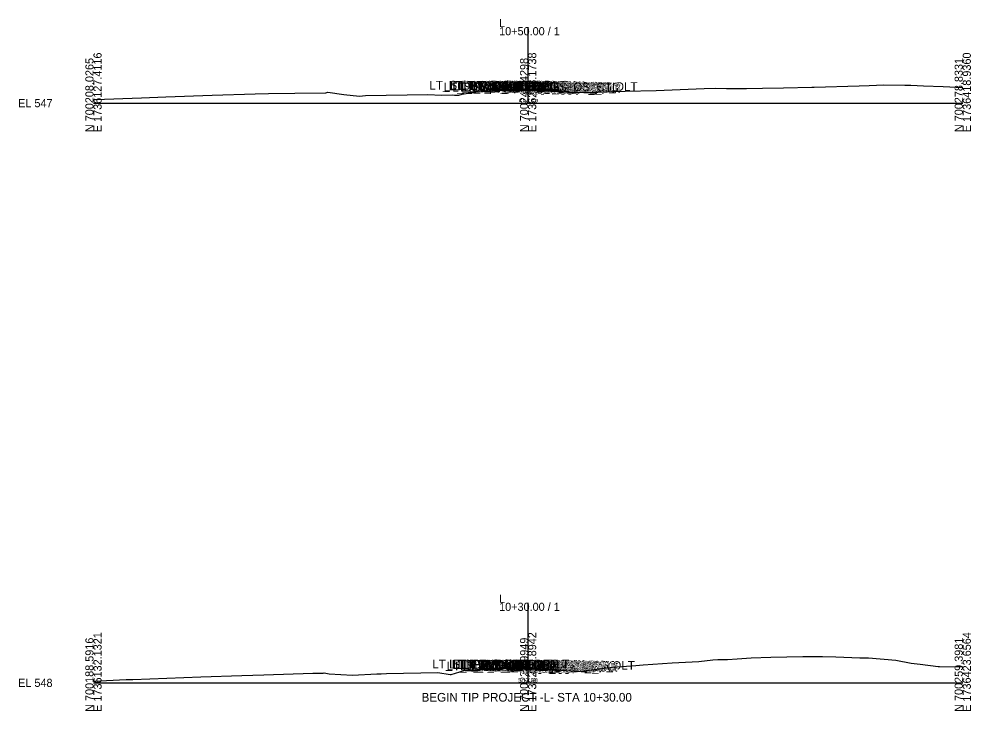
# Model space of a CAD drawing. Extents: x -26 to 697, y -10 to 2642.
# Drawn here: x -25.7 to 302.8, y -9.7 to 229 of the extents above; entities that cross this region are included whole.
import ezdxf

# ---------------------------------------------------------------- set-up
doc = ezdxf.new("R2010")
doc.units = 0
for name, color, linetype in [('Default', 7, 'Continuous'), ('Exist CMT Pavement', 7, 'Continuous'), ('Exist Cross Section Cell', 7, 'Continuous'), ('Exist XS Center Line Elevation Label', 7, 'Continuous'), ('Exist XS Ground Line', 7, 'Continuous'), ('Prop CMT Pvmt Course 1', 7, 'Continuous'), ('Prop CMT Pvmt Course 1 Wedge', 7, 'Continuous'), ('Prop CMT Pvmt Course 2', 7, 'Continuous'), ('Prop CMT Pvmt Course 2 Wedge', 7, 'Continuous'), ('Prop CMT Pvmt Surface', 7, 'Continuous'), ('Prop CMT Pvmt Surface Shoulder', 7, 'Continuous'), ('Prop CMT Pvmt Wedge Surface 1', 7, 'Continuous'), ('Prop CMT Pvmt Wedge Surface 2', 7, 'Continuous'), ('Prop CMT Shld Paved Course 1', 7, 'Continuous'), ('Prop CMT Shld Paved Course 2', 7, 'Continuous'), ('Prop CMT Slope Grass', 7, 'Continuous'), ('Prop CMT Subgrade Earthwork', 7, 'Continuous'), ('Prop XS SE Text', 7, 'Continuous'), ('Prop XS Side Slope Text', 7, 'Continuous'), ('Scratch_Level_1', 7, 'Continuous')]:
    doc.layers.add(name, color=color, linetype=linetype)

msp = doc.modelspace()

# ---------------------------------------------------------------- linework, layer by layer
at = {"layer": 'Exist CMT Pavement'}
for points in [[(150, 204.52), (140.21, 204.48)], [(140.21, 204.48), (145.1, 204.51)], [(145.1, 204.51), (150, 204.52)], [(155.38, 204.29), (150, 204.52)], [(150, 204.52), (160.77, 204.03)], [(160.77, 204.03), (155.38, 204.29)], [(150, 4.9), (140.24, 4.96)], [(140.24, 4.96), (145.12, 4.92)], [(145.12, 4.92), (150, 4.9)], [(154.91, 4.71), (150, 4.9)], [(150, 4.9), (159.83, 4.53)], [(159.83, 4.53), (154.91, 4.71)]]:
    msp.add_lwpolyline(points, dxfattribs=at)
at = {"layer": 'Exist Cross Section Cell'}
for p, q in [((150, 200), (150, 226.23)), ((0, 200), (150, 200)), ((150, 200), (300, 200)), ((150, 0), (150, 27.64)), ((0, 0), (150, 0)), ((150, 0), (300, 0))]:
    msp.add_line(p, q, dxfattribs=at)
at = {"layer": 'Exist XS Ground Line'}
for points in [[(0, 201.19), (0.59, 201.22), (16.62, 201.84), (24.98, 202.15), (40.94, 202.76), (55.81, 203.19), (60.46, 203.29), (69.46, 203.51), (80.19, 203.56), (80.83, 203.83), (86.45, 202.94), (91.86, 202.43), (93.87, 202.68), (115.45, 202.98), (120.08, 202.81), (123.78, 202.88), (124.56, 202.76), (126.09, 202.82), (127.21, 203.16), (130.72, 203.71), (134.46, 203.98), (140.21, 204.48), (141.2, 204.51), (149.87, 204.52), (151.5, 204.47), (162.09, 203.97), (165.52, 203.65), (172.32, 203.77), (174.03, 203.8), (180.31, 204), (183.46, 204.11), (194.19, 204.38), (210.71, 205.05), (214.65, 205.13), (218.43, 205.05), (225.41, 205.12), (230.86, 205.17), (238.16, 205.27), (247.87, 205.55), (248.69, 205.57), (264.2, 205.98), (267.71, 206.15), (272.78, 206.28), (280.07, 206.2), (282.14, 206.2), (286.51, 206.02), (293.22, 205.7), (300, 205.41)], [(0, 0.56), (11.33, 1.13), (13.59, 1.21), (37.02, 2.08), (51.16, 2.57), (58.82, 2.79), (75.74, 3.33), (79.3, 3.3), (79.63, 3.44), (81.37, 3.16), (89.44, 2.63), (97.84, 3.1), (99.33, 3.15), (101.12, 3.22), (118.87, 3.55), (123.13, 2.86), (123.44, 2.87), (127.98, 4.24), (128.94, 4.54), (135.7, 4.68), (140.24, 4.96), (141.9, 4.93), (149.9, 4.9), (158.4, 4.57), (159.83, 4.53), (160.25, 4.51), (162.4, 4.27), (164.5, 4.12), (167.14, 3.91), (172.89, 4.64), (176.41, 5.08), (179.14, 5.37), (187.14, 6.02), (189.66, 6.25), (199.74, 6.92), (208.96, 7.42), (213.75, 7.94), (215.52, 8.07), (218.79, 8.06), (222.17, 8.31), (226.93, 8.66), (233.76, 8.88), (244.87, 9.1), (250.06, 9.07), (251.57, 9.07), (256.23, 8.98), (264.51, 8.66), (267.45, 8.62), (276.88, 7.8), (282.24, 6.75), (285.31, 6.42), (291.52, 5.68), (291.94, 5.61), (300, 5.51)]]:
    msp.add_lwpolyline(points, dxfattribs=at)
at = {"layer": 'Prop CMT Pvmt Course 1'}
for points in [[(150, 204.77), (139.25, 204.78)], [(139.25, 204.78), (139.25, 204.57)], [(139.25, 204.57), (140.21, 204.57)], [(140.21, 204.57), (140.21, 204.67)], [(140.21, 204.67), (150, 204.67)], [(150, 204.56), (150, 204.77)], [(150, 204.77), (160.77, 204.35)], [(150, 204.56), (150, 204.77)], [(150, 204.67), (150, 204.56), (150, 204.56)], [(160.77, 204.25), (150, 204.67)], [(150, 204.67), (150, 204.56), (150, 204.56)], [(160.77, 204.35), (160.77, 204.14), (160.77, 204.14), (160.77, 204.25)], [(150, 5), (140.24, 5.04)], [(140.24, 5.04), (140.24, 4.83), (140.24, 4.83), (140.24, 4.93)], [(140.24, 4.93), (150, 4.9)], [(150, 4.8), (150, 5)], [(150, 5), (159.83, 4.62)], [(150, 4.8), (150, 5)], [(150, 4.9), (150, 4.8), (150, 4.8)], [(159.83, 4.52), (150, 4.9)], [(150, 4.9), (150, 4.8), (150, 4.8)], [(159.83, 4.62), (159.83, 4.41), (159.83, 4.41), (159.83, 4.52)]]:
    msp.add_lwpolyline(points, dxfattribs=at)
at = {"layer": 'Prop CMT Pvmt Course 1 Wedge'}
for points in [[(150, 204.67), (140.21, 204.67)], [(150, 204.67), (160.77, 204.25)], [(150, 4.9), (140.24, 4.93)], [(150, 4.9), (159.83, 4.52)]]:
    msp.add_lwpolyline(points, dxfattribs=at)
at = {"layer": 'Prop CMT Pvmt Course 2'}
for points in [[(140.21, 204.57), (139.25, 204.57)], [(139.25, 204.57), (139.25, 204.11)], [(139.25, 204.11), (140.21, 204.11)], [(140.21, 204.11), (140.21, 204.57)], [(160.77, 203.69), (160.77, 203.69), (160.77, 204.14), (160.77, 204.14)], [(160.77, 204.14), (160.77, 203.69)], [(140.24, 4.37), (140.24, 4.37), (140.24, 4.83), (140.24, 4.83)], [(140.24, 4.83), (140.24, 4.37)], [(159.83, 3.96), (159.83, 3.96), (159.83, 4.41), (159.83, 4.41)], [(159.83, 4.41), (159.83, 3.96)]]:
    msp.add_lwpolyline(points, dxfattribs=at)
at = {"layer": 'Prop CMT Pvmt Course 2 Wedge'}
for points in [[(150, 204.56), (140.21, 204.57)], [(150, 204.56), (160.77, 204.14)], [(150, 4.8), (140.24, 4.83)], [(150, 4.8), (159.83, 4.41)]]:
    msp.add_lwpolyline(points, dxfattribs=at)
at = {"layer": 'Prop CMT Pvmt Surface'}
for points in [[(150, 204.77), (139.25, 204.78)], [(150, 204.77), (160.77, 204.35)], [(150, 5), (140.24, 5.04)], [(150, 5), (159.83, 4.62)]]:
    msp.add_lwpolyline(points, dxfattribs=at)
at = {"layer": 'Prop CMT Pvmt Surface Shoulder'}
for points in [[(139.25, 204.78), (139.24, 204.78)], [(160.77, 204.35), (160.78, 204.35)], [(140.24, 5.04), (140.23, 5.04)], [(159.83, 4.62), (159.84, 4.62)]]:
    msp.add_lwpolyline(points, dxfattribs=at)
at = {"layer": 'Prop CMT Pvmt Wedge Surface 1'}
for points in [[(139.25, 204.57), (139.25, 204.78)], [(140.21, 204.57), (139.25, 204.57)], [(150, 204.67), (140.21, 204.67)], [(140.21, 204.67), (140.21, 204.57)], [(150, 204.77), (150, 204.56), (150, 204.56), (150, 204.67)], [(150, 204.77), (150, 204.56), (150, 204.56), (150, 204.67)], [(150, 204.67), (160.77, 204.25)], [(160.77, 204.14), (160.77, 204.35)], [(160.77, 204.25), (160.77, 204.14), (160.77, 204.14)], [(140.24, 4.83), (140.24, 5.04)], [(150, 4.9), (140.24, 4.93)], [(140.24, 4.93), (140.24, 4.83), (140.24, 4.83)], [(150, 5), (150, 4.8), (150, 4.8), (150, 4.9)], [(150, 5), (150, 4.8), (150, 4.8), (150, 4.9)], [(150, 4.9), (159.83, 4.52)], [(159.83, 4.41), (159.83, 4.62)], [(159.83, 4.52), (159.83, 4.41), (159.83, 4.41)]]:
    msp.add_lwpolyline(points, dxfattribs=at)
at = {"layer": 'Prop CMT Pvmt Wedge Surface 2'}
for points in [[(139.25, 204.57), (139.25, 204.78)], [(150, 204.56), (139.25, 204.57)], [(150, 204.77), (150, 204.56)], [(150, 204.77), (150, 204.56)], [(150, 204.56), (160.77, 204.14)], [(160.77, 204.14), (160.77, 204.35)], [(140.24, 4.83), (140.24, 5.04)], [(150, 4.8), (140.24, 4.83)], [(150, 5), (150, 4.8)], [(150, 5), (150, 4.8)], [(150, 4.8), (159.83, 4.41)], [(159.83, 4.41), (159.83, 4.62)]]:
    msp.add_lwpolyline(points, dxfattribs=at)
at = {"layer": 'Prop CMT Shld Paved Course 1'}
for points in [[(139.25, 204.78), (139.24, 204.78), (139.03, 204.57)], [(139.03, 204.57), (139.25, 204.57)], [(139.25, 204.57), (139.25, 204.78)], [(160.77, 204.35), (160.78, 204.35), (160.99, 204.14)], [(160.77, 204.14), (160.77, 204.35)], [(160.99, 204.14), (160.77, 204.14)], [(140.24, 5.04), (140.23, 5.04), (140.02, 4.83)], [(140.02, 4.83), (140.24, 4.83)], [(140.24, 4.83), (140.24, 5.04)], [(159.83, 4.62), (159.84, 4.62), (160.06, 4.4)], [(159.83, 4.41), (159.83, 4.62)], [(160.06, 4.4), (159.83, 4.41)]]:
    msp.add_lwpolyline(points, dxfattribs=at)
at = {"layer": 'Prop CMT Shld Paved Course 2'}
for points in [[(139.25, 204.57), (139.03, 204.57), (139.02, 204.57), (138.56, 204.11)], [(138.56, 204.11), (139.25, 204.11)], [(139.25, 204.11), (139.25, 204.57)], [(160.77, 204.14), (160.99, 204.14), (161, 204.14), (161.48, 203.66)], [(160.77, 203.69), (160.77, 204.14)], [(161.48, 203.66), (160.77, 203.69)], [(140.24, 4.83), (140.02, 4.83), (140.01, 4.83), (139.56, 4.37)], [(139.56, 4.37), (140.24, 4.37)], [(140.24, 4.37), (140.24, 4.83)], [(159.83, 4.41), (160.06, 4.4), (160.07, 4.4), (160.54, 3.93)], [(159.83, 3.96), (159.83, 4.41)], [(160.54, 3.93), (159.83, 3.96)]]:
    msp.add_lwpolyline(points, dxfattribs=at)
at = {"layer": 'Prop CMT Slope Grass'}
for points in [[(139.24, 204.78), (136.24, 204.6), (135.11, 204.03)], [(160.78, 204.35), (163.77, 204.11), (164.51, 203.74)], [(140.23, 5.04), (137.24, 4.87), (137.02, 4.76)], [(159.84, 4.62), (162.83, 4.38), (163.17, 4.21)]]:
    msp.add_lwpolyline(points, dxfattribs=at)
at = {"layer": 'Prop CMT Subgrade Earthwork'}
for points in [[(138.56, 204.11), (137.97, 204.7)], [(139.25, 204.11), (138.56, 204.11)], [(140.21, 204.11), (139.25, 204.11)], [(140.21, 204.11), (140.22, 204.49)], [(160.77, 203.69), (160.75, 204.03)], [(161.48, 203.66), (162.07, 204.25)], [(160.77, 203.69), (160.77, 203.69)], [(160.77, 203.69), (161.48, 203.66)], [(139.56, 4.37), (138.97, 4.97)], [(140.24, 4.37), (139.56, 4.37)], [(140.24, 4.37), (140.26, 4.96)], [(140.24, 4.37), (140.24, 4.37)], [(159.83, 3.96), (159.81, 4.53)], [(159.83, 3.96), (159.83, 3.96)], [(159.83, 3.96), (160.54, 3.93)], [(160.54, 3.93), (161.13, 4.52)]]:
    msp.add_lwpolyline(points, dxfattribs=at)
at = {"layer": 'Scratch_Level_1'}
for p, q in [((150, 204.67), (140.21, 204.67)), ((140.21, 204.67), (140.21, 204.57)), ((149.44, 204.52), (149.87, 204.52)), ((149.87, 204.52), (150, 204.52)), ((150, 204.52), (150, 204.67)), ((160.77, 204.25), (150, 204.67)), ((150, 204.67), (150, 204.52)), ((155.38, 204.29), (160.75, 204.03)), ((160.77, 204.14), (160.77, 204.25)), ((160.77, 204.03), (160.77, 204.14))]:
    msp.add_line(p, q, dxfattribs=at)
for points in [[(140.21, 204.57), (141.2, 204.56), (145.1, 204.54), (149.44, 204.52)], [(150, 204.52), (151.5, 204.47), (155.38, 204.29)], [(160.75, 204.03), (160.75, 204.03), (160.77, 204.03)]]:
    msp.add_lwpolyline(points, dxfattribs=at)

# ---------------------------------------------------------------- texts
at = {"layer": 'Default'}
for s, height, p in [('LT_Sub_Trench_Out_DLT', 3, (115.92, 204.7)), ('LT_Sub_Trench_Out', 3, (120.89, 204.11)), ('LT_GS_OS_CTL', 3, (122.64, 204.6)), ('LT_PV_Sub_Tie_Out', 3, (122.72, 204.49)), ('LT_PS2_Shelf_Out', 3, (122.99, 204.57)), ('LT_Slope_Fill', 3, (123.82, 204.03)), ('LT_PV_OEEOP_EG', 3, (124, 204.48)), ('LT_PV2_OEEOP', 3, (126.39, 204.57)), ('LT_PS2_OEOP', 3, (126.39, 204.57)), ('LT_Sub_OEEOP', 3, (126.46, 204.11)), ('LT_PV2_OEOT', 3, (126.48, 204.57)), ('LT_Sub_OEOT', 3, (126.56, 204.11)), ('LT_PV1_OEEOP', 3, (126.74, 204.67)), ('LT_PV1_OEOT', 3, (126.84, 204.78)), ('LT_PS1_OEOP', 3, (126.96, 204.78)), ('LT_PV_EG_TestPt', 3, (130.23, 204.51)), ('RT_PV_IEEOP_EG', 3, (134.76, 204.52)), ('LT_PV_IEEOP_EG', 3, (134.93, 204.52)), ('RT_PV2_IEEOP', 3, (137.14, 204.56)), ('LT_PV2_IEEOP', 3, (137.32, 204.56)), ('RT_PV1_IEEOP', 3, (137.5, 204.67)), ('LT_PV1_IEEOP', 3, (137.68, 204.67)), ('RT_Sub_Trench_Out_DLT', 3, (139.84, 204.25)), ('RT_PV_EG_TestPt', 3, (140.33, 204.29)), ('PV2_PGL', 3, (142.05, 204.56)), ('PV1_PGL', 3, (142.41, 204.77)), ('RT_PV_Sub_Tie_Out', 3, (143.07, 204.03)), ('RT_PV_OEEOP_EG', 3, (144.38, 204.03)), ('RT_PS2_Shelf_Out', 3, (144.8, 204.14)), ('RT_PV2_OEEOP', 3, (146.77, 204.14)), ('RT_PV1_OEEOP', 3, (147.13, 204.25)), ('RT_PV2_OEOT', 3, (147.82, 204.14)), ('RT_PS2_OEOP', 3, (148.18, 204.14)), ('RT_PV1_OEOT', 3, (148.18, 204.35)), ('RT_PS1_OEOP', 3, (148.32, 204.35)), ('RT_GS_OS_CTL', 3, (149.98, 204.11)), ('RT_Sub_Trench_Out', 3, (143.63, 203.66)), ('RT_Sub_OEEOP', 3, (146.84, 203.69)), ('RT_Sub_OEOT', 3, (147.9, 203.69)), ('RT_Slope_Fill', 3, (153.05, 203.74)), ('-', 0.0001, (0, 200)), ('LT_Sub_Trench_Out_DLT', 3, (116.92, 4.97)), ('LT_Sub_Trench_Out', 3, (121.89, 4.37)), ('LT_PV_Sub_Tie_Out', 3, (122.75, 4.96)), ('LT_GS_OS_CTL', 3, (123.63, 4.87)), ('LT_PS2_Shelf_Out', 3, (123.99, 4.83)), ('LT_PV_OEEOP_EG', 3, (124.03, 4.96)), ('LT_Slope_Fill', 3, (125.73, 4.76)), ('LT_PV2_OEEOP', 3, (126.42, 4.83)), ('LT_Sub_OEEOP', 3, (126.49, 4.37)), ('LT_PV1_OEEOP', 3, (126.78, 4.93)), ('LT_PS2_OEOP', 3, (127.38, 4.83)), ('LT_PV2_OEOT', 3, (127.48, 4.83)), ('LT_Sub_OEOT', 3, (127.55, 4.37)), ('LT_PV1_OEOT', 3, (127.84, 5.04)), ('LT_PS1_OEOP', 3, (127.95, 5.04)), ('LT_PV_EG_TestPt', 3, (130.24, 4.92)), ('RT_PV_IEEOP_EG', 3, (134.76, 4.9)), ('LT_PV_IEEOP_EG', 3, (134.93, 4.9)), ('RT_PV2_IEEOP', 3, (137.14, 4.8)), ('LT_PV2_IEEOP', 3, (137.32, 4.8)), ('RT_PV1_IEEOP', 3, (137.5, 4.9)), ('LT_PV1_IEEOP', 3, (137.68, 4.9)), ('RT_Sub_Trench_Out_DLT', 3, (138.9, 4.52)), ('RT_PV_EG_TestPt', 3, (139.86, 4.71)), ('PV2_PGL', 3, (142.05, 4.8)), ('RT_PV_Sub_Tie_Out', 3, (142.13, 4.53)), ('PV1_PGL', 3, (142.41, 5)), ('RT_Sub_Trench_Out', 3, (142.69, 3.93)), ('RT_PV_OEEOP_EG', 3, (143.44, 4.53)), ('RT_PS2_Shelf_Out', 3, (143.86, 4.4)), ('RT_PV2_OEEOP', 3, (145.83, 4.41)), ('RT_Sub_OEEOP', 3, (145.9, 3.96)), ('RT_PV1_OEEOP', 3, (146.19, 4.52)), ('RT_PV2_OEOT', 3, (146.89, 4.41)), ('RT_Sub_OEOT', 3, (146.96, 3.96)), ('RT_PS2_OEOP', 3, (147.24, 4.4)), ('RT_PV1_OEOT', 3, (147.25, 4.62)), ('RT_PS1_OEOP', 3, (147.38, 4.62)), ('RT_GS_OS_CTL', 3, (149.05, 4.38)), ('RT_Slope_Fill', 3, (151.71, 4.21)), ('-', 0.0001, (0, 0))]:
    msp.add_text(s, height=height, dxfattribs=at).set_placement(p)
at = {"layer": 'Exist Cross Section Cell'}
for s, p in [('L', (140, 226.23)), ('10+50.00 / 1', (140, 223.43)), ('EL 547', (-26, 198.6)), ('L', (140, 27.64)), ('10+30.00 / 1', (140, 24.84)), ('EL 548', (-26, -1.4))]:
    msp.add_text(s, height=2.8, dxfattribs=at).set_placement(p)
for s, p in [('E 1736127.4116', (2.8, 190)), ('E 1736273.1738', (152.8, 190)), ('E 1736418.9360', (302.8, 190)), ('N 700208.0265', (0, 190)), ('N 700243.4298', (150, 190)), ('N 700278.8331', (300, 190)), ('E 1736132.1321', (2.8, -10)), ('E 1736277.8942', (152.8, -10)), ('E 1736423.6564', (302.8, -10)), ('N 700188.5916', (0, -10)), ('N 700223.9949', (150, -10)), ('N 700259.3981', (300, -10))]:
    msp.add_text(s, height=2.8, rotation=90, dxfattribs=at).set_placement(p)
at = {"layer": 'Exist XS Center Line Elevation Label'}
for s, p in [('551.52', (146.82, 199.72)), ('552.90', (146.57, 0.1))]:
    msp.add_text(s, height=1.6, dxfattribs=at).set_placement(p)
at = {"layer": 'Prop XS SE Text'}
for s, rotation, p in [('0.001', 359.9685, (141.49, 205.78)), ('0.039', 357.7666, (151.95, 205.7)), ('EXIST.', 0.4775, (140.48, 5.37)), ('EXIST.', 357.8524, (151.53, 5.37))]:
    msp.add_text(s, height=2, rotation=rotation, dxfattribs=at).set_placement(p)
at = {"layer": 'Prop XS Side Slope Text'}
for rotation, p in [(26.5651, (133.92, 204.28)), (333.4349, (163.06, 205.31)), (26.5651, (135.37, 4.65)), (333.4349, (161.75, 5.54))]:
    msp.add_text('2:1', height=2, rotation=rotation, dxfattribs=at).set_placement(p)
msp.add_text('BEGIN TIP PROJECT -L- STA 10+30.00', height=3, dxfattribs=at).set_placement((113.23, -6.48))

doc.saveas('drawing.dxf')
